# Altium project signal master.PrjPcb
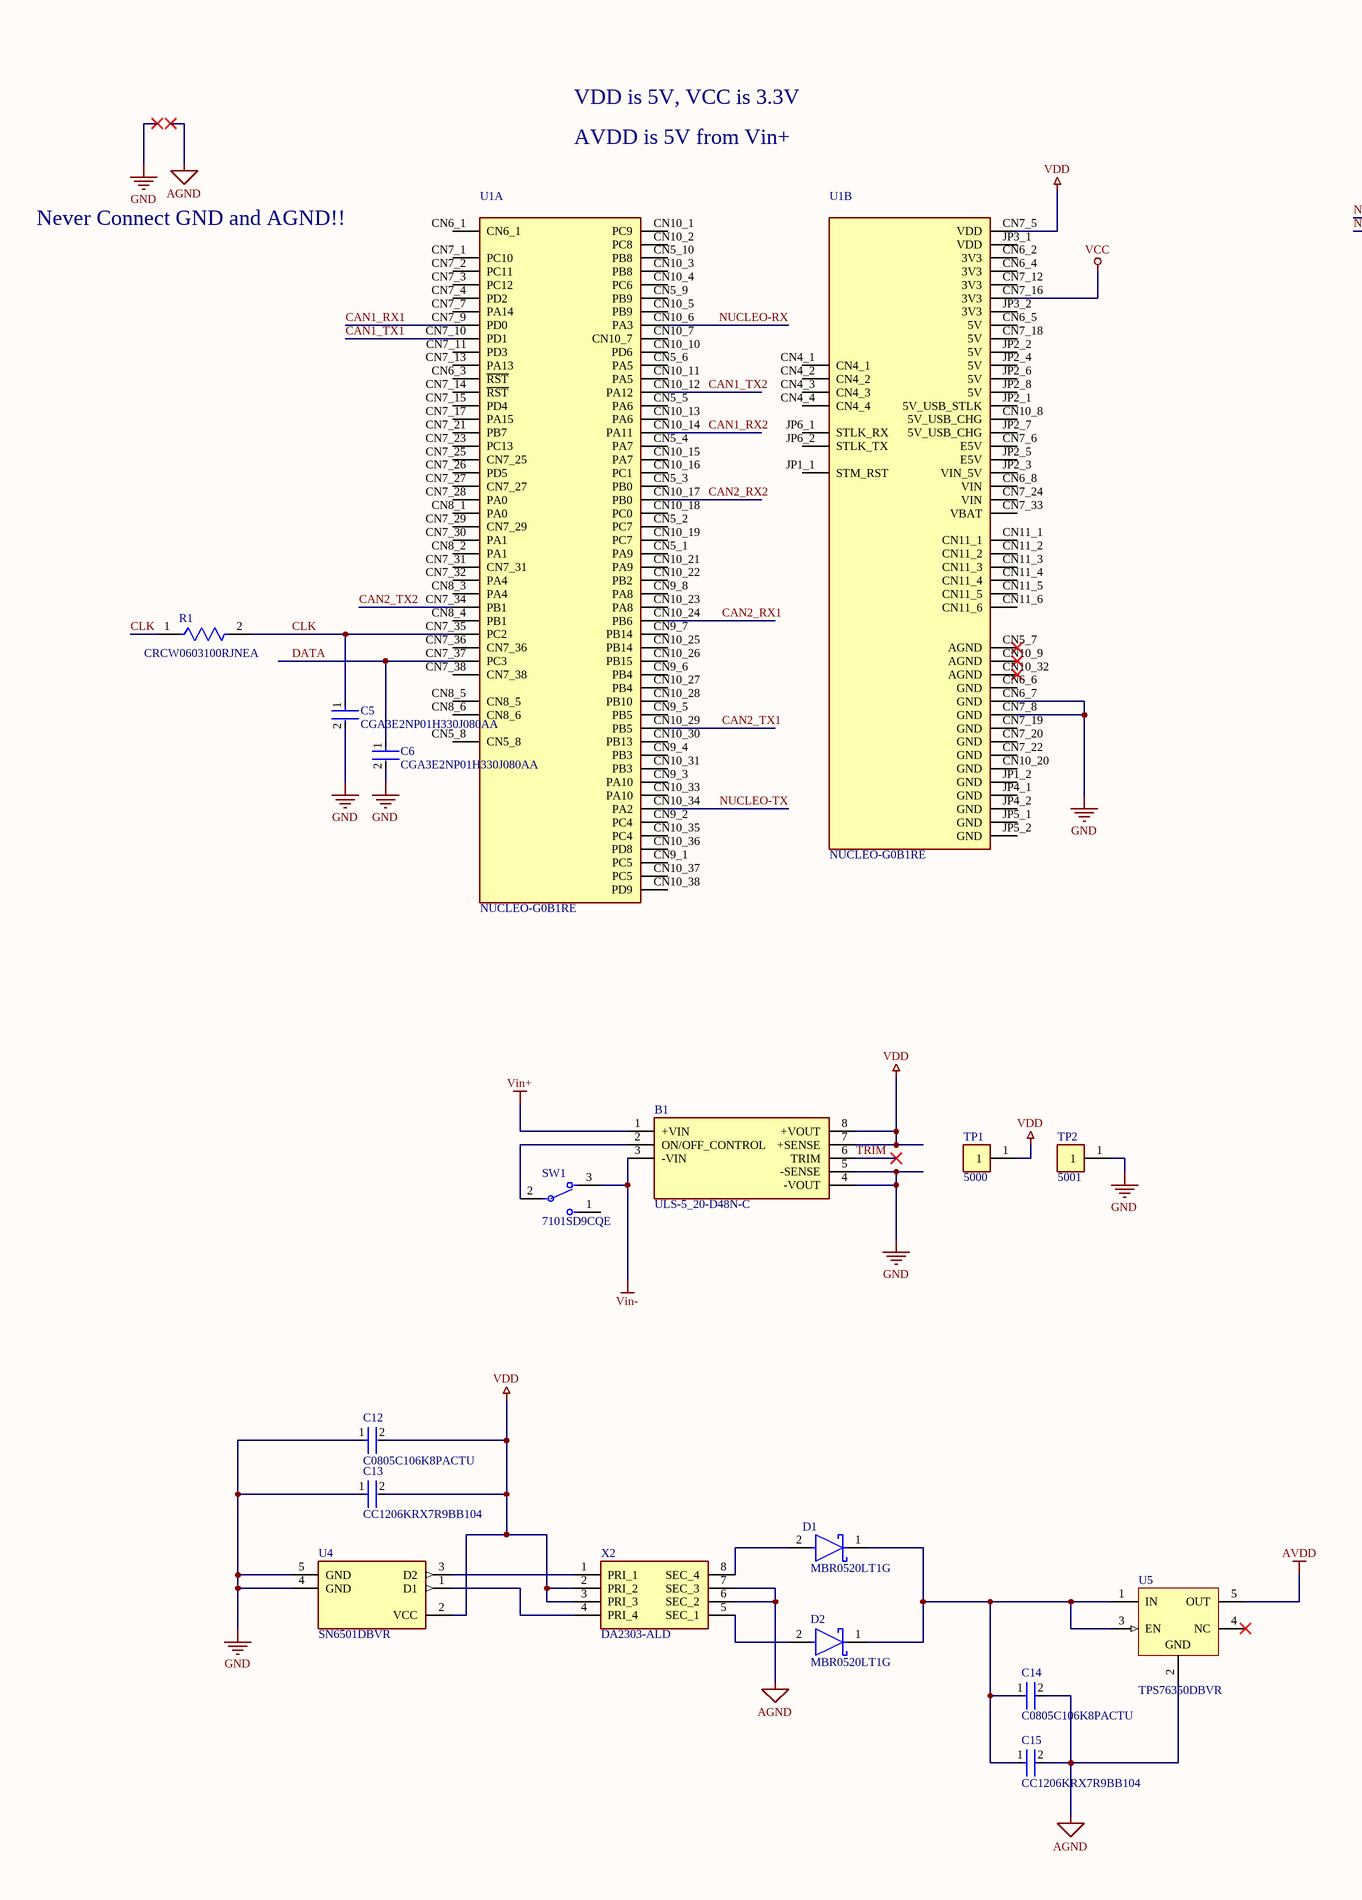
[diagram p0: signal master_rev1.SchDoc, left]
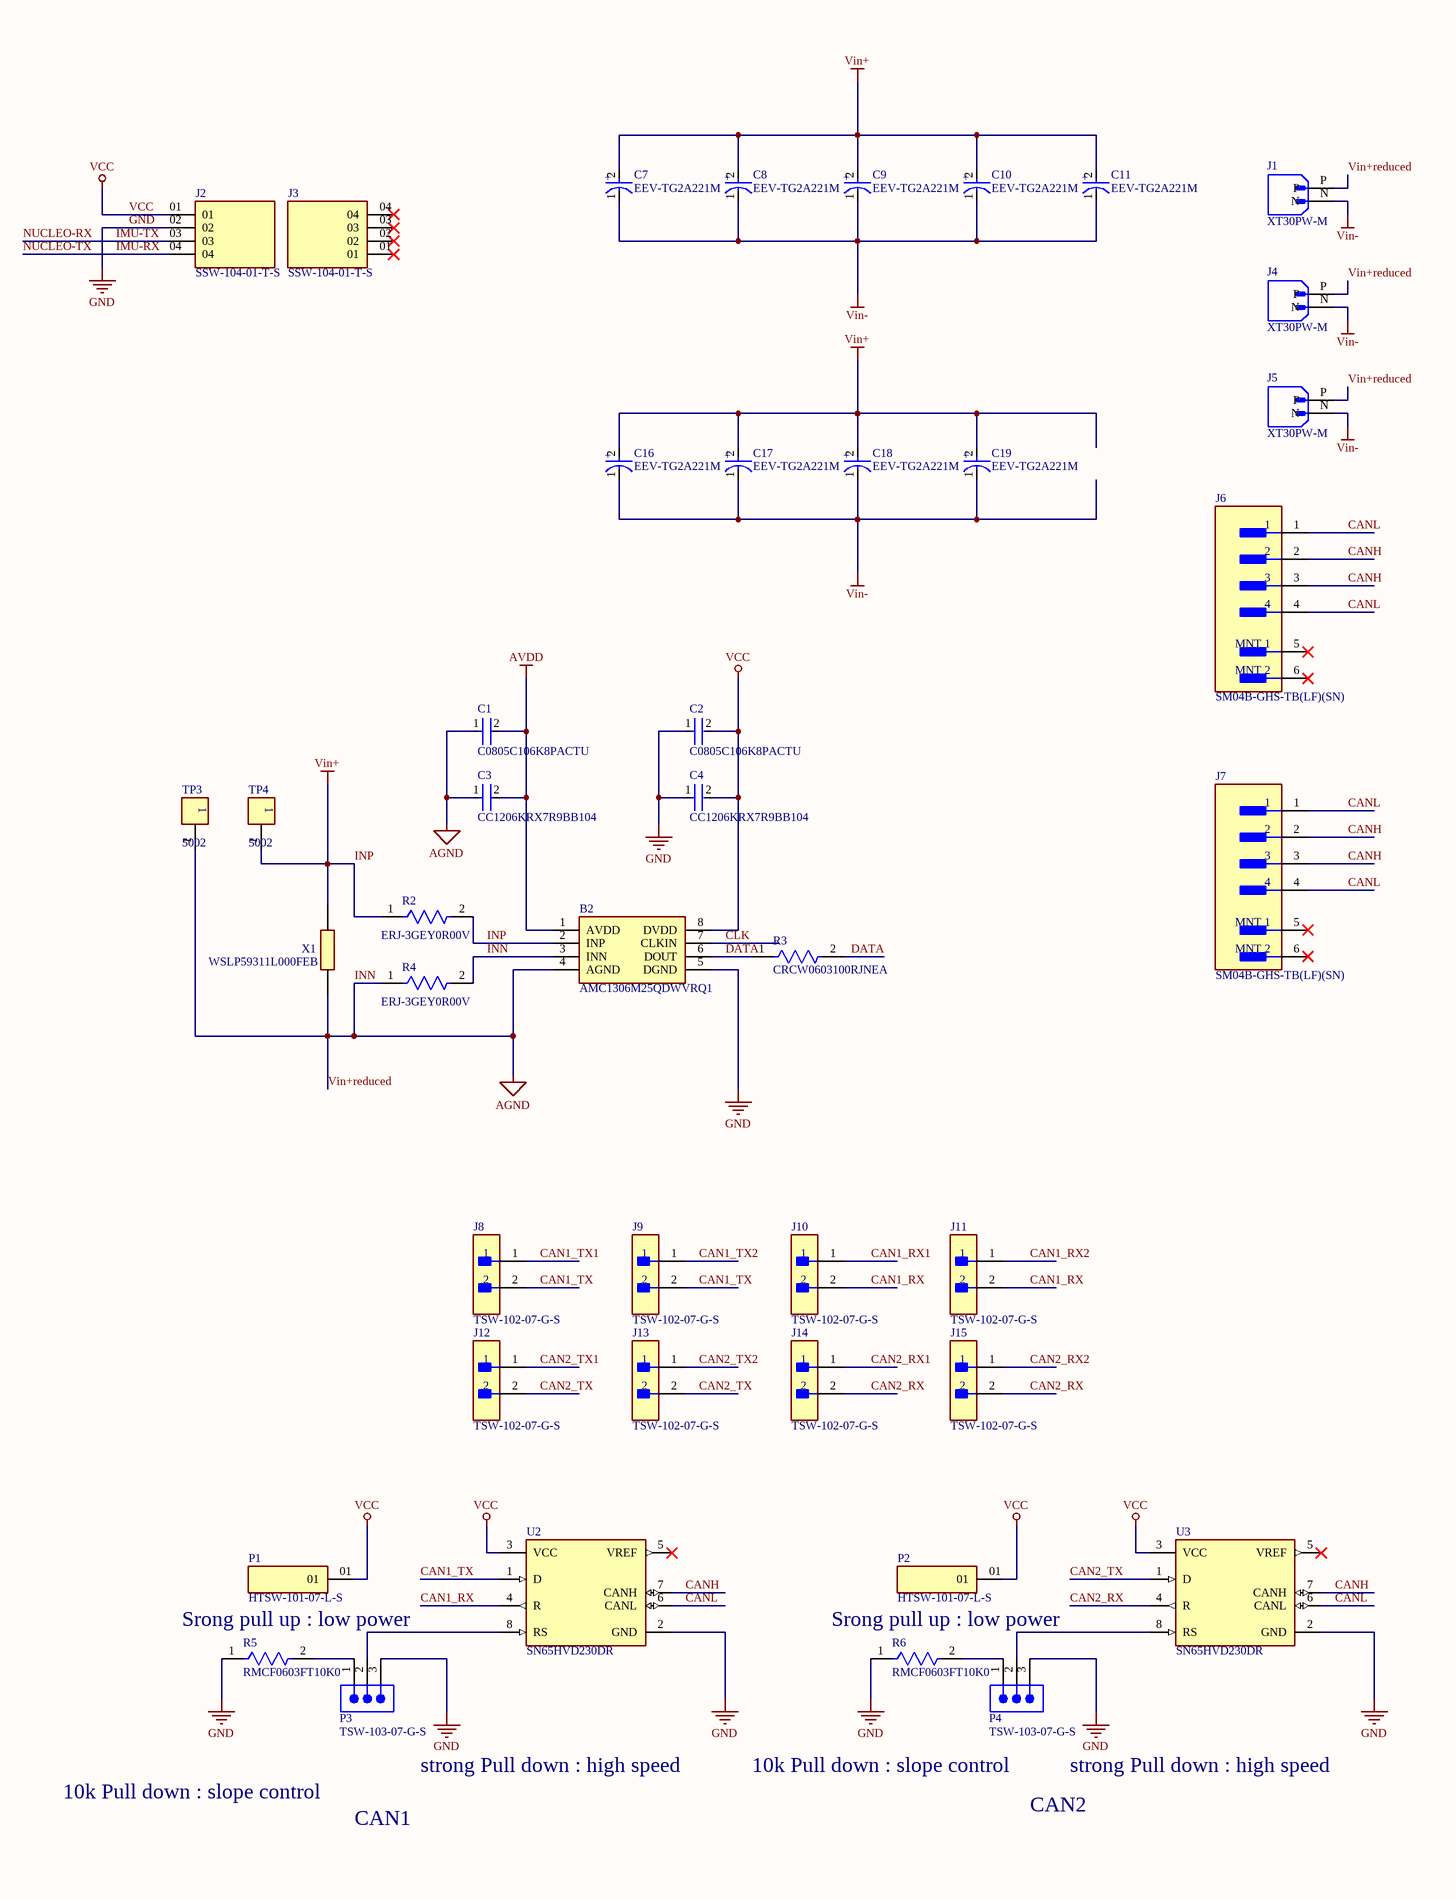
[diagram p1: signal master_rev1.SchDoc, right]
1 sheet, 60 parts. Net scope: global (net labels, ports and power ports of the same name join across sheets).
Board file: signal master.PcbDoc

## Sheet signal master_rev1.SchDoc
size A2; SheetNumber: 1; SheetTotal: 1

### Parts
B1  ULS-5_20-D48N-C  [ULS520D48NC]
B2  AMC1306M25QDWVRQ1  [SOIC127P1150X280-8N]
C1  C0805C106K8PACTU  [FP-C0805C-DG-MFG]
C2  C0805C106K8PACTU  [FP-C0805C-DG-MFG]
C3  CC1206KRX7R9BB104  [FP-CC1206-1_25-MFG]
C4  CC1206KRX7R9BB104  [FP-CC1206-1_25-MFG]
C5  CGA3E2NP01H330J080AA  [FP-CGA3E-0_3-0_1-MFG]
C6  CGA3E2NP01H330J080AA  [FP-CGA3E-0_3-0_1-MFG]
C7  EEV-TG2A221M  [FP-TG-K16-MFG]
C8  EEV-TG2A221M  [FP-TG-K16-MFG]
C9  EEV-TG2A221M  [FP-TG-K16-MFG]
C10  EEV-TG2A221M  [FP-TG-K16-MFG]
C11  EEV-TG2A221M  [FP-TG-K16-MFG]
C12  C0805C106K8PACTU  [FP-C0805C-DG-MFG]
C13  CC1206KRX7R9BB104  [FP-CC1206-1_25-MFG]
C14  C0805C106K8PACTU  [FP-C0805C-DG-MFG]
C15  CC1206KRX7R9BB104  [FP-CC1206-1_25-MFG]
C16  EEV-TG2A221M  [FP-TG-K16-MFG]
C17  EEV-TG2A221M  [FP-TG-K16-MFG]
C18  EEV-TG2A221M  [FP-TG-K16-MFG]
C19  EEV-TG2A221M  [FP-TG-K16-MFG]
D1  MBR0520LT1G  [FP-425-04-IPC_C]
D2  MBR0520LT1G  [FP-425-04-IPC_C]
J1  XT30PW-M  [AMASS_XT30PW-M]
J2  SSW-104-01-T-S  [SAMTEC_SSW-104-01-T-S]
J3  SSW-104-01-T-S  [SAMTEC_SSW-104-01-T-S]
J4  XT30PW-M  [AMASS_XT30PW-M]
J5  XT30PW-M  [AMASS_XT30PW-M]
J6  SM04B-GHS-TB(LF)(SN)  [FP-SM04B-GHS-TB_LF_SN-MFG]
J7  SM04B-GHS-TB(LF)(SN)  [FP-SM04B-GHS-TB_LF_SN-MFG]
J8  TSW-102-07-G-S  [FP-TSW-102-07-G-S-MFG]
J9  TSW-102-07-G-S  [FP-TSW-102-07-G-S-MFG]
J10  TSW-102-07-G-S  [FP-TSW-102-07-G-S-MFG]
J11  TSW-102-07-G-S  [FP-TSW-102-07-G-S-MFG]
J12  TSW-102-07-G-S  [FP-TSW-102-07-G-S-MFG]
J13  TSW-102-07-G-S  [FP-TSW-102-07-G-S-MFG]
J14  TSW-102-07-G-S  [FP-TSW-102-07-G-S-MFG]
J15  TSW-102-07-G-S  [FP-TSW-102-07-G-S-MFG]
P1  HTSW-101-07-L-S  [SAMTEC_HTSW-101-07-L-S]
P2  HTSW-101-07-L-S  [SAMTEC_HTSW-101-07-L-S]
P3  TSW-103-07-G-S  [SMTC-TSW-103-07-X-S]
P4  TSW-103-07-G-S  [SMTC-TSW-103-07-X-S]
R1  CRCW0603100RJNEA  [FP-CRCW0603-e3-IPC_B]
R2  ERJ-3GEY0R00V  [FP-ERJ-3GEY0R00V-MFG]
R3  CRCW0603100RJNEA  [FP-CRCW0603-e3-IPC_B]
R4  ERJ-3GEY0R00V  [FP-ERJ-3GEY0R00V-MFG]
R5  RMCF0603FT10K0  [FP-RMCF0603-MFG]
R6  RMCF0603FT10K0  [FP-RMCF0603-MFG]
SW1  7101SD9CQE  [FP-7101SD9CQE-MFG]
TP1  5000  [FP-5000-MFG]
TP2  5001  [FP-5001-MFG]
TP3  5002  [FP-5002-MFG]
TP4  5002  [FP-5002-MFG]
U1  NUCLEO-G0B1RE  [MODULE_NUCLEO-G0B1RE]  (parts A,B of 2)
U2  SN65HVD230DR  [FP-D0008A-IPC_A]
U3  SN65HVD230DR  [FP-D0008A-IPC_A]
U4  SN6501DBVR  [FP-DBV0005A-IPC_C]
U5  TPS76350DBVR  [DBV0005A_M]
X1  WSLP59311L000FEB  [WSLP59311L000FEB]
X2  DA2303-ALD  [DA2303ALD]

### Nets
AVDD: B2.1(AVDD) C1.2 C3.2 U5.5(OUT)
GND: B1.4(-VOUT) B1.5(-SENSE) B2.5(DGND) C2.1 C4.1 C5.2 C6.2 C12.1 C13.1 J2.02 P3.3 P4.3 R5.1 R6.1 TP2.1 U1.CN6_7(GND) U1.CN7_8(GND) U2.2(GND) U3.2(GND) U4.4(GND) U4.5(GND)
INN: B2.3(INN) B2.4(AGND) C1.1 C3.1 C14.2 C15.2 J1.P J4.P J5.P R4.1 R4.2 TP3.1 U5.2(GND) X1.1 X2.6(SEC_2) X2.7(SEC_3)  [also labelled AGND, Vin+reduced]
INP: B1.1(+VIN) B2.2(INP) C7.2(A) C8.2(A) C9.2(A) C10.2(A) C11.2(A) C16.2(A) C17.2(A) C18.2(A) C19.2(A) R2.1 R2.2 TP4.1 X1.2  [also labelled Vin+]
VCC: B2.8(DVDD) C2.2 C4.2 J2.01 P1.01 P2.01 U1.CN7_16(3V3) U2.3(VCC) U3.3(VCC)
VDD: B1.7(+SENSE) B1.8(+VOUT) C12.2 C13.2 TP1.1 U1.CN7_5(VDD) U4.2(VCC) X2.2(PRI_2) X2.3(PRI_3)
Vin-: B1.3(-VIN) C7.1(C) C8.1(C) C9.1(C) C10.1(C) C11.1(C) C16.1(C) C17.1(C) C18.1(C) C19.1(C) J1.N J4.N J5.N SW1.3
CAN1_RX: J10.2 J11.2 U2.4(R)
CAN1_RX1: J10.1 U1.CN7_9(PD0)
CAN1_RX2: J11.1 U1.CN10_14(PA11)
CAN1_TX: J8.2 J9.2 U2.1(D)
CAN1_TX1: J8.1 U1.CN7_10(PD1)
CAN1_TX2: J9.1 U1.CN10_12(PA12)
CAN2_RX: J14.2 J15.2 U3.4(R)
CAN2_RX1: J14.1 U1.CN10_24(PB6)
CAN2_RX2: J15.1 U1.CN10_17(PB0)
CAN2_TX: J12.2 J13.2 U3.1(D)
CAN2_TX1: J12.1 U1.CN10_29(PB5)
CAN2_TX2: J13.1 U1.CN7_34(PB1)
CANH: J6.2 J6.3 J7.2 J7.3 U2.7(CANH) U3.7(CANH)
CANL: J6.1 J6.4 J7.1 J7.4 U2.6(CANL) U3.6(CANL)
CLK: B2.7(CLKIN) C5.1 R1.1 R1.2 U1.CN7_35(PC2)
DATA: B2.6(DOUT) C6.1 R3.1 R3.2 U1.CN7_37(PC3)
IMU-RX: J2.04 U1.CN10_34(PA2)  [also labelled NUCLEO-TX]
IMU-TX: J2.03 U1.CN10_6(PA3)  [also labelled NUCLEO-RX]
TRIM: B1.6(TRIM)
NetB1_2: B1.2(ON/OFF_CONTROL) SW1.2(COMM)
NetC14_1: C14.1 C15.1 D1.1(C) D2.1(C) U5.1(IN) U5.3(EN)
NetD1_2: D1.2(A) X2.8(SEC_4)
NetD2_2: D2.2(A) X2.5(SEC_1)
NetP3_1: P3.1 R5.2
NetP3_2: P3.2 U2.8(RS)
NetP4_1: P4.1 R6.2
NetP4_2: P4.2 U3.8(RS)
NetU4_1: U4.1(D1) X2.4(PRI_4)
NetU4_3: U4.3(D2) X2.1(PRI_1)

Not connected (* = marked no-connect by the designer): J3 01* 02* 03* 04*; J6 5(MNT_1)* 6(MNT_2)*; J7 5(MNT_1)* 6(MNT_2)*; SW1 1; U1 CN4_1 CN4_2 CN4_3 CN4_4 CN5_1(PA9) CN5_2(PC7) CN5_3(PB0) CN5_4(PA7) CN5_5(PA6) CN5_6(PA5) CN5_7(AGND)* CN5_8 CN5_9(PB9) CN5_10(PB8) CN6_1 CN6_2(3V3) CN6_3(~{RST}) CN6_4(3V3) CN6_5(5V) CN6_6(GND) CN6_8(VIN) CN7_1(PC10) CN7_2(PC11) CN7_3(PC12) CN7_4(PD2) CN7_6(E5V) CN7_7(PA14) CN7_11(PD3) CN7_12(3V3) CN7_13(PA13) CN7_14(~{RST}) CN7_15(PD4) CN7_17(PA15) CN7_18(5V) CN7_19(GND) CN7_20(GND) CN7_21(PB7) CN7_22(GND) CN7_23(PC13) CN7_24(VIN) CN7_25 CN7_26(PD5) CN7_27 CN7_28(PA0) CN7_29 CN7_30(PA1) CN7_31 CN7_32(PA4) CN7_33(VBAT) CN7_36 CN7_38 CN8_1(PA0) CN8_2(PA1) CN8_3(PA4) CN8_4(PB1) CN8_5 CN8_6 CN9_1(PC5) CN9_2(PC4) CN9_3(PA10) CN9_4(PB3) CN9_5(PB5) CN9_6(PB4) CN9_7(PB14) CN9_8(PA8) CN10_1(PC9) CN10_2(PC8) CN10_3(PB8) CN10_4(PC6) CN10_5(PB9) CN10_7 CN10_8(5V_USB_CHG) CN10_9(AGND)* CN10_10(PD6) CN10_11(PA5) CN10_13(PA6) CN10_15(PA7) CN10_16(PC1) CN10_18(PC0) CN10_19(PC7) CN10_20(GND) CN10_21(PA9) CN10_22(PB2) CN10_23(PA8) CN10_25(PB14) CN10_26(PB15) CN10_27(PB4) CN10_28(PB10) CN10_30(PB13) CN10_31(PB3) CN10_32(AGND)* CN10_33(PA10) CN10_35(PC4) CN10_36(PD8) CN10_37(PC5) CN10_38(PD9) CN11_1 CN11_2 CN11_3 CN11_4 CN11_5 CN11_6 JP1_1(STM_RST) JP1_2(GND) JP2_1(5V_USB_STLK) JP2_2(5V) JP2_3(VIN_5V) JP2_4(5V) JP2_5(E5V) JP2_6(5V) JP2_7(5V_USB_CHG) JP2_8(5V) JP3_1(VDD) JP3_2(3V3) JP4_1(GND) JP4_2(GND) JP5_1(GND) JP5_2(GND) JP6_1(STLK_RX) JP6_2(STLK_TX); U2 5(VREF)*; U3 5(VREF)*; U5 4(NC)*

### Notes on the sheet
- VDD is 5V, VCC is 3.3V
- AVDD is 5V from Vin+
- Never Connect GND and AGND!!
- Srong pull up : low power
- strong Pull down : high speed
- 10k Pull down : slope control
- CAN1
- CAN2

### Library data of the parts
B1 = CMP-013-000001-1: Isolated DC/DC Converters 100W 48Vin 5Vout 20A Neg Log; Manufacturer_Name: Murata Electronics; Manufacturer_Part_Number: ULS-5/20-D48N-C; Geometry.Height: 10.16mm
B2 = CMP-026-000000-1: Data Acquisition ADCs/DACs - Specialized Automotive, +/-250-mV input, precision reinforced isolated modulator with CMOS interface; Manufacturer_Name: Texas Instruments; Geometry.Height: 2.8mm
C1 C2 C12 C14 = CMP-2007-03243-2: CAP CER 10UF 10V X5R 0805; Manufacturer: Kemet; 3DS Part Number: 220-00001; Tolerance: 10%; Temperature Coefficient: 15%; Material: Ceramic
C3 C4 C13 C15 = CMP-03422-000842-1: CAP CER 0.1UF 50V X7R 1206; Manufacturer: Yageo; Automotive Grade: NA; Value: 100 nF; Tolerance: 0.1; Material: Ceramic; Temperature Coefficient: 15%
C5 C6 = CMP-08246-000318-1: Cap Ceramic 33pF 50V NP0 5% Pad SMD 0603 +150°C Automotive T/R; Dielectric: C0G
C7-C11 C16-C19 = CMP-00287-39480903-1: Cap Aluminum 220uF 100V 20% (18 X 16.5mm) SMD 0.28 Ohm 400mA 2000 hr 125°C T/R; Leakage Current: 220µA; ESR (Equivalent Series Resistance): 280mΩ; Life (Hours): 2000hours; Dissipation Factor: 10%; Capacitance: 220µF
D1 D2 = CMP-1055-00425-2: DIODE SCHOTTKY 20V 500MA SOD123; Polarity: Standard; Peak Non-Repetitive Surge Current: 5.5A; Forward Voltage: 385mV; Element Configuration: Single; Peak Reverse Current: 250uA
J1 J4 J5 = CMP-002-000003-1: Socket; DC supply; XT30; male; PIN: 2; on PCBs; THT; Colour: yellow; MF: AMASS
J2 J3 = CMP-002-000002-1: SSW - Samtec 2.54mm Single Row Straight Socket Strip 8.5 Profile - Fast Stock; MF: Samtec Inc.
J6 J7 = CMP-17439-000411-1: CONN HEADER SMD R/A 4POS 1.25MM; Voltage Rating: 50V; Number of Contacts: 4; Current Rating: 1A
J8-J15 = CMP-02766-000084-1: CONN HEADER VERT 2POS 2.54MM; Manufacturer: Samtec; Number Of Contacts: 2; Voltage Rating: 550V; Conn Orientation: Straight; Current Rating: 6.3A; Conn Gender: Male
P1 P2 = CMP-030-000000-1
P3 P4 = CMP-1024-00333-1: 0.025" SQ Post Header, Through-hole, Vertical, -55 to 125 degC, 2.54 mm Pitch, 3-Pin, Male, RoHS; Manufacturer: Samtec; Pitch: 2.54 mm
R1 R3 = CMP-2000-03827-2: RES Thick Film, 100Ω, 5%, 0.1W, 200ppm/°C, 0603; Power Rating: 100mW; Voltage Rating: 75V; Resistance: 100R
R2 R4 = CMP-2000-00700-2: RES SMD 0 OHM JUMPER 1/10W 0603; Manufacturer: Panasonic; Tolerance: 5%; Automotive Grade: Grade 0; Voltage Rating: 75V; Value: 0Ω; Temperature Coefficient: -100/+600ppm/°C; Power Rating: 0.1W
R5 R6 = CMP-2000-06990-2: 10kΩ ±1% 0.1W 0603 Thick Film Chip Resistor AEC-Q200 compliant; Max Power Dissipation: 100mW; Resistance: 10kR; Temperature Coefficient: 100ppm/°C
SW1 = CMP-01151-55410166-1: 7101SD9CQE Toggle Switch, Spdt, On-On, Maintained, 5A, 28Vdc, 3 Pcb Hole Cnt, Solder Terminal, Toggle; Voltage Rating (AC): 120V; Max Voltage Rating (DC): 28V; Illumination Type: Illuminated, Non-Illuminated; Contact Resistance: 10mΩ; Actuator Material: Brass, Chrome; Life (Cycles): 100kcycles; Max Voltage Rating (AC): 250V; Actuator Length: 12.45mm
TP1 = CMP-19636-000027-1: PC TEST POINT MINIATURE RED; Outside Diameter: 2.54mm; Body Material: Bronze; Number of Contacts: 1; Insulation: Insulated; Inside Diameter: 1.27mm; Hole Diameter: 1.6mm; Plating: Silver
TP2 = CMP-2000-05181-2: PC TEST POINT MINIATURE BLACK; Body Material: Bronze; Plating: Silver; Inside Diameter: 1.27mm; Hole Diameter: 1.6mm; Number of Ports: 1; Outside Diameter: 2.54mm; Insulation: Insulated
TP3 TP4 = CMP-2000-05182-2: PC TEST POINT MINIATURE WHITE; Body Material: Bronze; Insulation: Insulated; Inside Diameter: 1.27mm; Number of Ports: 1; Outside Diameter: 2.54mm; Hole Diameter: 1.6mm; Plating: Silver
U1 = CMP-018-000001-1: STM32G0B1RET6 Microcontroller Development Tool 0.032768MHz CPU 512KB Flash Win 7/Win 8/Win 10/Linux 64bit/Mac; MF: STMicroelectronics
U2 U3 = CMP-0315-00015-3: IC TRANSCEIVER HALF 1/1 8SOIC; Number of Transceivers: 1; Operating Supply Voltage: 3.3V; Number of I/Os: 2; Max Supply Current: 17mA; Max Supply Voltage: 3.6V; Min Supply Voltage: 3V; Data Rate: 1Mbps
U4 = CMP-2000-07129-2: IC REG CONV PWR SUPPLIES SOT23-5; Output Voltage: 11V; Number of Outputs: 1; Min Supply Voltage: 3V; Max Supply Voltage: 5.5V; Max Output Current: 350mA; Output Type: Adjustable; Switching Frequency: 620kHz; Operating Supply Current: 300uA; Output Current: 250mA
U5 = CMP-0394-00610-2: Single Output LDO, 150 mA, Fixed 5 V Output, 2.7 to 10 V Input, with Low IQ, 5-pin SOT-23 (DBV), -40 to 125 degC, Green (RoHS & no Sb/Br); Manufacturer: Texas Instruments; Vout Adj(Min)(V): 5; SubFamily: Single Channel LDO; Vdo(Typ)(mV): 300; Vin(Max)(V): 10; Accuracy(%): 3; Vin(Min)(V): 2.7; Iout(Max)(A): 0.15; Iq(Typ)(mA): 0.08
X1 = CMP-024-000000-1: Res Metal Strip 5931 0.001 Ohm 1% 10W +/-75ppm/C Pad SMD; Manufacturer_Name: Vishay; Geometry.Height: 0.5mm
X2 = CMP-032-000000-1: SMT Power Transformer; Manufacturer_Name: COILCRAFT; Geometry.Height: 5.97mm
